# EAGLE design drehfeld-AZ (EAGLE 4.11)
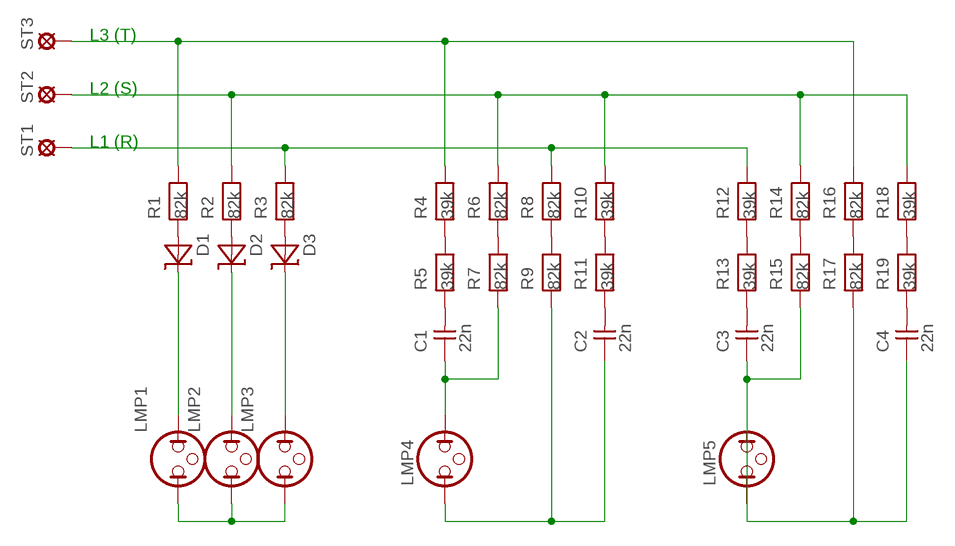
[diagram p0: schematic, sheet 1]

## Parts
C1  22n  CAPNP-10  [C-10]
C2  22n  CAPNP-10  [C-10]
C3  22n  CAPNP-10  [C-10]
C4  22n  CAPNP-10  [C-10]
D1  ZDIO-10  [D-10]
D2  ZDIO-10  [D-10]
D3  ZDIO-10  [D-10]
LMP1  NEON  [LDH-3R]
LMP2  NEON  [LDH-3R]
LMP3  NEON  [LDH-3R]
LMP4  NEON  [LDH-3R]
LMP5  NEON  [LDH-3R]
R1  82k  RESEU-10  [R-10]
R2  82k  RESEU-10  [R-10]
R3  82k  RESEU-10  [R-10]
R4  39k  RESEU-10  [R-10]
R5  39k  RESEU-10  [R-10]
R6  82k  RESEU-10  [R-10]
R7  82k  RESEU-10  [R-10]
R8  82k  RESEU-10  [R-10]
R9  82k  RESEU-10  [R-10]
R10  39k  RESEU-10  [R-10]
R11  39k  RESEU-10  [R-10]
R12  39k  RESEU-10  [R-10]
R13  39k  RESEU-10  [R-10]
R14  82k  RESEU-10  [R-10]
R15  82k  RESEU-10  [R-10]
R16  82k  RESEU-10  [R-10]
R17  82k  RESEU-10  [R-10]
R18  39k  RESEU-10  [R-10]
R19  39k  RESEU-10  [R-10]
ST1  SE13  [SE13]
ST2  SE13  [SE13]
ST3  SE13  [SE13]

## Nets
N$1: R4.1 R5.2
N$2: C1.2 R5.1
N$3: R6.1 R7.2
N$4: R8.1 R9.2
N$5: C2.2 R11.1
N$6: R10.1 R11.2
N$7: C3.2 R13.1
N$8: R12.1 R13.2
N$9: D1.1(A) R1.1
N$10: D2.1(A) R2.1
N$11: D3.1(A) R3.1
N$12: R14.1 R15.2
N$13: R16.1 R17.2
N$14: C4.2 R19.1
N$15: R18.1 R19.2
N$16: R1.2 R4.2 R16.2 ST3.MP
N$17: R2.2 R6.2 R10.2 R14.2 R18.2 ST2.MP
N$18: R3.2 R8.2 R12.2 ST1.MP
N$19: D1.2(K) LMP1.2
N$20: D2.2(K) LMP2.2
N$21: D3.2(K) LMP3.2
N$22: LMP1.1 LMP2.1 LMP3.1
N$23: C1.1 LMP4.2 R7.1
N$25: C2.1 LMP4.1 R9.1
N$26: C3.1 LMP5.1 R15.1
N$27: C4.1 LMP5.2 R17.1

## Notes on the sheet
- L3 (T)
- L2 (S)
- L1 (R)

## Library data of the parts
C1-C4 = discrete:CAPNP-10
D1-D3 = discrete:ZDIO-10
LMP1-LMP5 = special:NEON: Neon LAMP
R1-R19 = discrete:RESEU-10
ST1-ST3 = solpad:SE13: SOLDER PAD

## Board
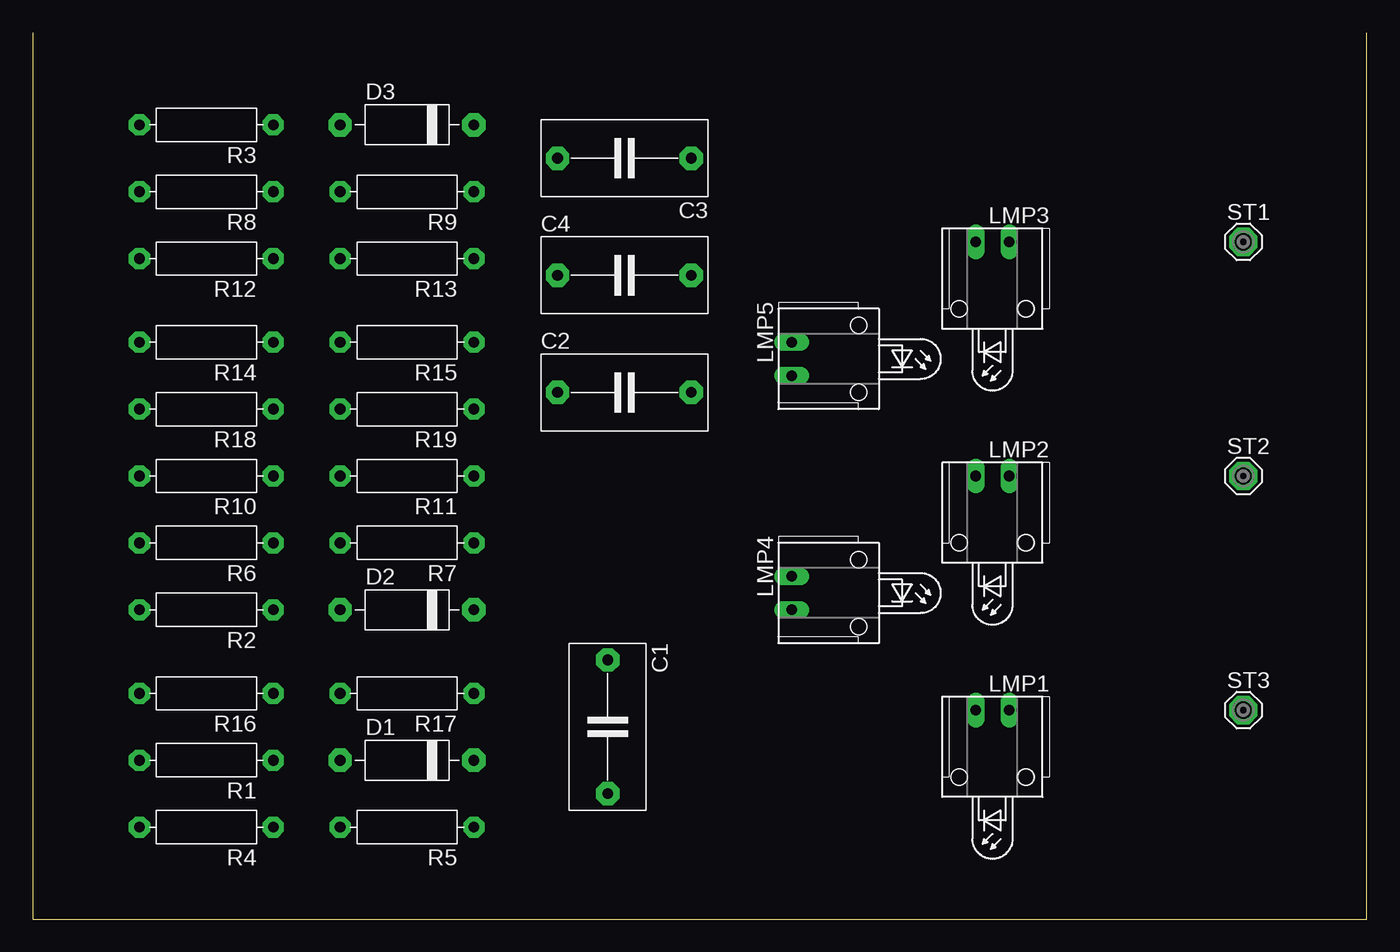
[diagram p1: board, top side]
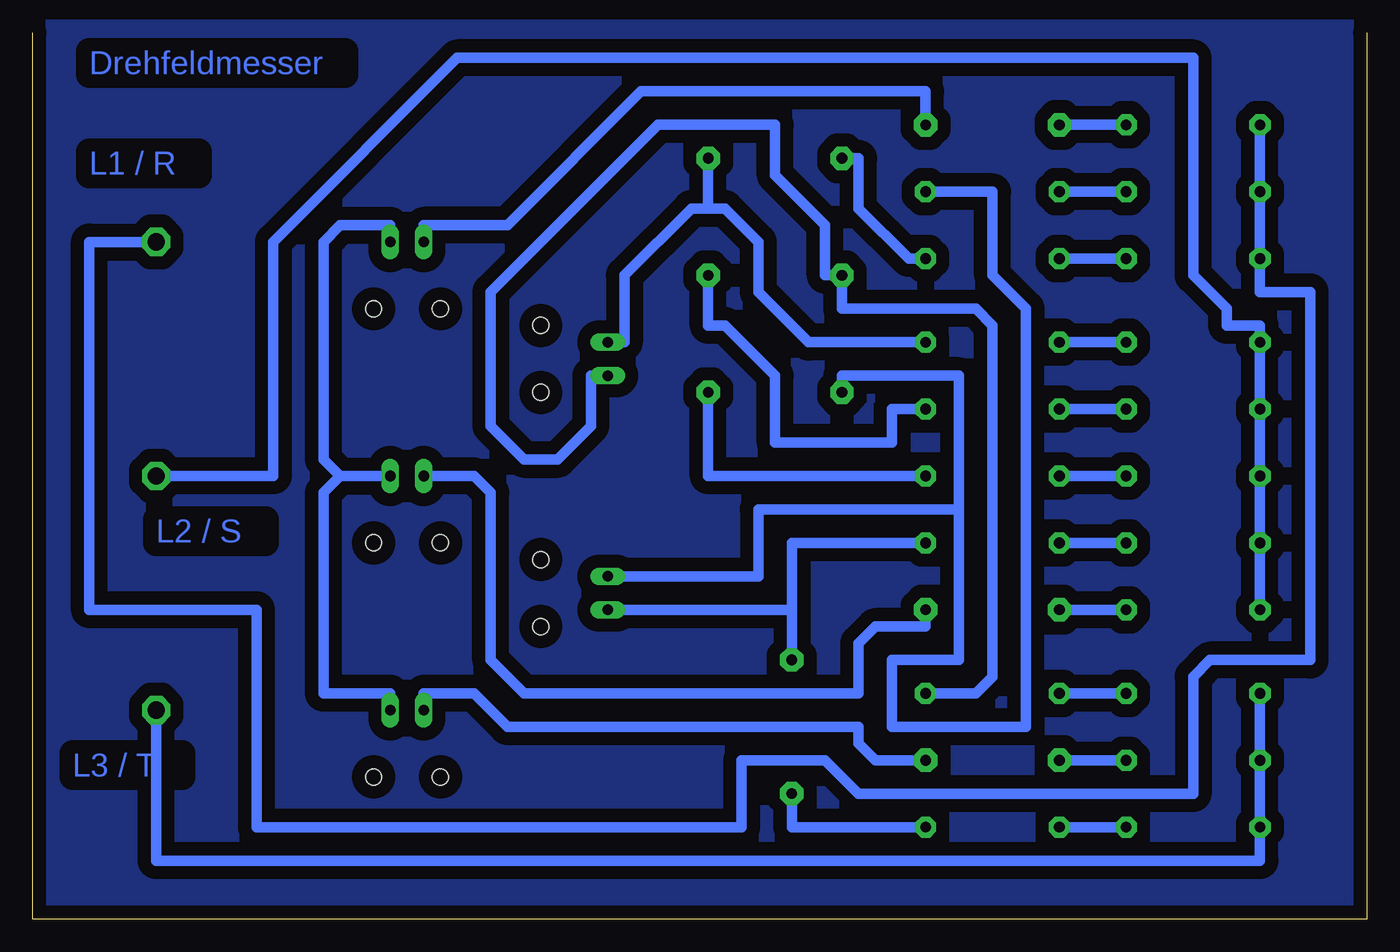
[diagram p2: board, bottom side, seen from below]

Size 101.27 x 67.3 mm. Coordinates in mm from the lower left corner, seen from the top.
Outline: 101.27,67.3 101.27,0 0,0 0,67.3
Copper layers (1*16): Top 0.035mm / dielectric 1.5mm / Bottom 0.035mm
Design rules "default": minimum track width 0.8mm, minimum drill 24mil, track to track 1mm, track to pad 1mm, pad to pad 8mil, via to via 8mil, smd to smd 8mil, copper to edge 40mil, drill to drill 8mil, minimum pad ring 10mil, minimum via ring 8mil, stop-mask expansion 4mil, vias tented up to drill 0mil, thermal gap 10mil

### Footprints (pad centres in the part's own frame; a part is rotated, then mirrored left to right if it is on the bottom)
C-10 = drill 0.813 pad 1.778 octagon: 1 -5.08,0; 2 5.08,0
D-10 = drill 0.813 pad 1.778 octagon: 1 -5.08,0; 2 5.08,0
LDH-3R = drill 0.813 long: 1 -1.27,-5.08; 2 1.27,-5.08 | hole 1.219: 2.54,0; -2.54,0
R-10 = drill 0.813 pad 1.6 octagon: 1 -5.08,0; 2 5.08,0
SE13 = drill 1.321 pad 2.159 octagon: MP 0,0

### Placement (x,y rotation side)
C1  43.65,14.6 270 top
C2  44.92,40 0 top
C3  44.92,57.78 180 top
C4  44.92,48.89 0 top
D1  28.41,12.06 0 top
D2  28.41,23.49 0 top
D3  28.41,60.32 0 top
LMP1  72.86,10.79 180 top
LMP2  72.86,28.57 180 top
LMP3  72.86,46.35 180 top
LMP4  62.7,24.76 270 top
LMP5  62.7,42.54 270 top
R1  13.17,12.06 180 top
R2  13.17,23.49 180 top
R3  13.17,60.32 180 top
R4  13.17,6.98 180 top
R5  28.41,6.98 180 top
R6  13.17,28.57 180 top
R7  28.41,28.57 180 top
R8  13.17,55.24 180 top
R9  28.41,55.24 180 top
R10  13.17,33.65 180 top
R11  28.41,33.65 180 top
R12  13.17,50.16 180 top
R13  28.41,50.16 180 top
R14  13.17,43.81 180 top
R15  28.41,43.81 180 top
R16  13.17,17.14 180 top
R17  28.41,17.14 180 top
R18  13.17,38.73 180 top
R19  28.41,38.73 180 top
ST1  91.91,51.43 0 top
ST2  91.91,33.65 0 top
ST3  91.91,15.87 0 top

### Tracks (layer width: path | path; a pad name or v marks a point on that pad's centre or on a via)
N$1
  Bottom 0.8: R4.1 R5.2
N$2
  Bottom 0.8: R5.1 43.65,6.98 C1.2
N$3
  Bottom 0.8: R6.1 R7.2
N$4
  Bottom 0.8: R8.1 R9.2
N$5
  Bottom 0.813: R11.1 50,33.65 C2.2
N$6
  Bottom 0.8: R10.1 R11.2
N$7
  Bottom 0.8: R13.1 34.76,50.16 38.57,53.97 38.57,57.78 C3.2
N$8
  Bottom 0.8: R12.1 R13.2
N$9
  Bottom 0.8: R1.1 D1.1
N$10
  Bottom 0.8: R2.1 D2.1
N$11
  Bottom 0.8: R3.1 D3.1
N$12
  Bottom 0.8: R14.1 R15.2
N$13
  Bottom 0.8: R16.1 R17.2
N$14
  Bottom 0.8: R19.1 36.03,38.73 36.03,36.19 44.92,36.19 44.92,41.27 48.73,45.08 50,45.08 C4.2
N$15
  Bottom 0.8: R18.1 R19.2
N$16
  Bottom 0.8: R16.2 R1.2 R4.2 8.09,4.44 91.91,4.44 ST3.MP
N$17
  Bottom 0.8: R2.2 R6.2 R10.2 R18.2 R14.2 8.09,45.08 10.63,45.08 10.63,46.35 13.17,48.89 13.17,65.4 69.05,65.4 83.02,51.43 83.02,33.65 ST2.MP
N$18
  Bottom 0.8: R3.2 R8.2 R12.2 8.09,47.62 4.28,47.62 4.28,19.68 11.9,19.68 13.17,18.41 13.17,9.52 38.57,9.52 41.11,12.06 47.46,12.06 47.46,6.98 84.29,6.98 84.29,23.49 96.99,23.49 96.99,51.43 ST1.MP
N$19
  Bottom 0.8: D1.2 37.3,12.06 38.57,13.33 38.57,14.6 65.24,14.6 67.78,17.14 71.59,17.14 LMP1.2
N$20
  Bottom 0.8: LMP2.2 67.78,33.65 66.51,32.38 66.51,19.68 63.97,17.14 38.57,17.14 38.57,20.95 37.3,22.22 33.49,22.22 D2.2
N$21
  Bottom 0.8: D3.2 33.49,62.86 55.08,62.86 65.24,52.7 71.59,52.7 LMP3.2
N$22
  Bottom 0.8: 77.94,33.65 79.21,32.38 79.21,17.14 74.13,17.14 LMP1.1 | 77.94,33.65 LMP2.1 | 77.94,33.65 79.21,34.92 79.21,51.43 77.94,52.7 74.13,52.7 LMP3.1
N$23
  Bottom 0.8: 43.65,23.49 C1.1 | 43.65,23.49 LMP4.2 | R7.1 43.65,28.57 43.65,23.49
N$24
  pour Bottom: -0.8,67.94 102.07,67.94 102.07,-0.64 -0.8,-0.64
N$25
  Bottom 0.8: 30.95,31.11 46.19,31.11 46.19,26.03 LMP4.1 | 30.95,31.11 30.95,41.27 39.84,41.27 C2.1 | R9.1 28.41,55.24 28.41,48.89 25.87,46.35 25.87,14.6 36.03,14.6 36.03,19.68 30.95,19.68 30.95,31.11
N$26
  Bottom 0.8: 50,53.97 51.27,53.97 56.35,48.89 56.35,43.81 LMP5.1 | 50,53.97 C3.1 | R15.1 42.38,43.81 46.19,47.62 46.19,51.43 48.73,53.97 50,53.97
N$27
  Bottom 0.8: LMP5.2 58.89,41.27 58.89,37.46 61.43,34.92 63.97,34.92 66.51,37.46 66.51,47.62 53.81,60.32 44.92,60.32 44.92,56.51 41.11,52.7 41.11,48.89 C4.1 39.84,46.35 29.68,46.35 28.41,45.08 28.41,18.41 29.68,17.14 R17.1

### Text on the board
Bottom: Drehfeldmesser | L1 / R | L2 / S | L3 / T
